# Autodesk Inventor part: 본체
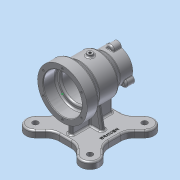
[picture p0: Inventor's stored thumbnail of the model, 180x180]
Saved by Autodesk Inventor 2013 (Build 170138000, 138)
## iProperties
Created: 2017-03
Part Number: 본체
Material: 알루미늄 6061
Document SubType Name: Modeling
Designer: Administrator
Density: 2.71 g/cm^3
Mass: 995.698 g
Surface Area: 858.98 cm^2
Volume: 367.416 cm^3
Author: Administrator
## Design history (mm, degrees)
sketch "스케치1"
  geometry: 1 further point
sketch "스케치2"
  geometry: L1 (0, 0)-(100, 0); L2 (0, 35)-(23, 35); L3 (23, 35)-(23, 26); L4 (23, 26)-(70, 26); L5 (70, 26)-(70, 17.5); L6 (70, 17.5)-(100, 17.5); L7 (100, 17.5)-(100, 27.5); L8 (100, 27.5)-(77, 27.5); L9 (77, 27.5)-(65, 36); L10 (65, 36)-(31, 36); L11 (31, 36)-(20, 45); L12 (20, 45)-(0, 45); L13 (0, 45)-(0, 35)
  constraints: 26 end point, 8 parallel, 2 perpendicular, 2 point on line, 1 horizontal
  dimensions: "d0" = 100 distance of L1.start L1.end; "d1" = 35 diameter of L6 L1; "d2" = 52 diameter of L4 L1; "d3" = 70 diameter of L2 L1; "d4" = 55 diameter of L8 L1; "d5" = 72 diameter of L10 L1; "d6" = 90 diameter of L12 L1; "d7" = 23 distance between parallel lines of L3 L13; "d8" = 47 distance between parallel lines of L5 L3; "d9" = 20 distance of L11.end L12.end; "d10" = 31 distance from line of L10.end L13; "d11" = 65 distance from line of L13 L9.end; "d12" = 23 distance of L7.end L8.end
revolve "회전1" sketch "스케치2" stored, may be unused: angle "d13" = 90 deg
chamfer "모따기1" distance "d25" = 1; stored, may be unused: second distance "d26" = 2, angle "d27" = 45 deg
node "작업 평면1"
sketch "스케치4"
  geometry: L1 (45, 5)-(-45, 5); L2 (-45, 5)-(-45, 95); L3 (-45, 95)-(45, 95); L4 (45, 95)-(45, 5); L5 (45, 5)-(-45, 95); L6 (-45, 5)-(45, 95); 2 further points
  constraints: 12 end point, 2 midpoint, 2 parallel, 1 horizontal, 1 perpendicular
  dimensions: "d29" = 90 distance of L2.end L3.end; "d31" = 90 distance of L1.end L2.end; "d32" = 0 horizontal distance of point (0, 0) point (0, 50); "d33" = 50 distance of point (0, 0) point (0, 50)
extrude "돌출2" join sketch "스케치4" distance "d34" = 12; taper "d35" = 0 deg
sketch "스케치5" dims "d36" = 140
  geometry: L1 (45, 5)-(-45, 5) reference; L2 (45, 95)-(45, 5) reference; L3 (-45, 95)-(45, 95) reference; L4 (-45, 5)-(-45, 95) reference; L5 (-45, 50)-(45, 50); L6 (0, 95)-(0, 5); L7 (49.497, 99.497)-(0, 50); L8 (24.042, 50)-(61.518, 87.477); L9 (0, 74.042)-(37.477, 111.518); A1 r 17 centre (49.497, 99.497) between (37.477, 111.518) and (61.518, 87.477); 1 further point
  constraints: 10 end point, 5 midpoint, 2 point on circle, 2 point on line, 2 tangent, 1 centre point, 3 other
  dimensions: "d38" = 45 deg angle of L5 L7; "d40" = 34 diameter of A1; "d41" = 45 deg angle of L5 L8; "d42" = 45 deg angle of L6 L9
extrude "돌출3" join sketch "스케치5" distance "d43" = 12; taper "d44" = 0 deg
sketch "스케치6"
  geometry: L1 (-45, 5)-(45, 5) reference; L2 (45, 5)-(45, 95) reference; C1 r 0.5 at (0, 50); 1 further point
  constraints: 1 centre point
  dimensions: "d45" = 45 distance from line of L1 C1.centre; "d46" = 45 distance from line of L2 C1.centre; "d47" = 1 diameter of C1
extrude "돌출4" join sketch "스케치6" distance "d48" = 5; taper "d49" = 0 deg
fillet "모깎기3" dims "d53" = 25
fillet "모깎기4" dims "d54" = 3
fillet "모깎기5" dims "d55" = 3
chamfer "모따기2" distance "d56" = 1; stored, may be unused: second distance "d57" = 2, angle "d58" = 45 deg
node "작업 평면2"
sketch "스케치11"
  geometry: L1 (-4, 87)-(4, 87); L2 (4, 87)-(4, 13); L3 (4, 13)-(-4, 13); L4 (-4, 13)-(-4, 87); L5 (-4, 87)-(4, 13); L6 (4, 87)-(-4, 13); C1 r 0.5 at (0, 50) reference; 1 further point
  constraints: 12 end point, 2 midpoint, 2 parallel, 1 horizontal, 1 perpendicular
  dimensions: "d85" = 8 distance between parallel lines of L4 L2; "d87" = 74 distance between parallel lines of L1 L3
extrude "돌출7" join sketch "스케치11" stored distance "d88" = 8; taper "d89" = 0 deg
node "작업 평면3"
sketch "스케치12"
  geometry: L1 (-4, -70)-(4, -70) reference; L2 (4, -70)-(-4, -70) reference; L3 (-30.402, -70)-(-10.603, -70) reference; L4 (-39.598, -70)-(-30.402, -70) reference; L5 (-59.397, -70)-(-39.598, -70) reference; L6 (-50.201, -70)-(-59.397, -70) reference; L7 (-42, -70)-(-50.201, -70) reference; L8 (-50.201, -70)-(-42, -70) reference; L9 (-59.397, -70)-(-50.201, -70) reference; L10 (-39.598, -70)-(-59.397, -70) reference; L11 (-30.402, -70)-(-39.598, -70) reference; L12 (-10.603, -70)-(-30.402, -70) reference; L13 (10.603, -70)-(-10.603, -70) reference; L14 (30.402, -70)-(10.603, -70) reference; L15 (39.598, -70)-(30.402, -70) reference; L16 (59.397, -70)-(39.598, -70) reference; L17 (50.201, -70)-(59.397, -70) reference; L18 (42, -70)-(50.201, -70) reference; L19 (50.201, -70)-(42, -70) reference; L20 (59.397, -70)-(50.201, -70) reference; L21 (39.598, -70)-(59.397, -70) reference; L22 (30.402, -70)-(39.598, -70) reference; L23 (10.603, -70)-(30.402, -70) reference; L24 (-10.603, -70)-(10.603, -70) reference; L25 (-25, -70)-(-18.14, -31.096); A1 r 36 centre (0, 0) between (4, -35.777) and (-4, -35.777) reference; A2 r 36 centre (0, 0) between (4, -35.777) and (-4, -35.777) reference; 1 further point
  constraints: 2 end point, 2 point on circle, 1 point on line
  dimensions: "d91" = 25 horizontal distance of point (0, 0) L25.start; "d92" = 100 deg angle of L11 L25
feature "리브3" sketch "스케치12" dims "d93" = 1, "d94" = 4, "d95" = 0, "d96" = 0, "d97" = 1, "d98" = 1
sketch "스케치13"
  geometry: L1 (-10.603, -70)-(-30.402, -70) reference; L2 (-25, -70)-(-18.14, -31.096); A1 r 36 centre (0, 0) between (4, -35.777) and (-4, -35.777) reference; 1 further point
  constraints: 2 end point, 1 point on circle, 1 point on line
  dimensions: "d99" = 25 horizontal distance of point (0, 0) L2.start; "d100" = 100 deg angle of L1 L2
feature "리브4" sketch "스케치13" dims "d101" = 1, "d102" = 4, "d103" = 0, "d104" = 0, "d105" = 1, "d106" = 1
sketch "스케치14"
  geometry: L1 (30.402, -70)-(10.603, -70) reference; L2 (25, -70)-(18.14, -31.096); A1 r 36 centre (0, 0) between (4, -35.777) and (-4, -35.777) reference; 1 further point
  constraints: 2 end point, 1 point on circle, 1 point on line
  dimensions: "d107" = 25 horizontal distance of point (0, 0) L2.start; "d108" = 100 deg angle of L1 L2
feature "리브5" sketch "스케치14" dims "d109" = 1, "d110" = 4, "d111" = 0, "d112" = 0, "d113" = 1, "d114" = 1
sketch "스케치15"
  geometry: L1 (4, -70)-(25, -70) reference; L2 (30.402, -70)-(10.603, -70) reference; L3 (25, -70)-(18.14, -31.096); A1 r 36 centre (0, 0) between (4, -35.777) and (-4, -35.777) reference; 1 further point
  constraints: 2 end point, 1 point on circle, 1 point on line
  dimensions: "d115" = 25 horizontal distance of point (0, 0) L3.start; "d116" = 100 deg angle of L1 L3
feature "리브6" sketch "스케치15" dims "d117" = 1, "d118" = 4, "d119" = 0, "d120" = 0, "d121" = 1, "d122" = 1
fillet "모깎기8" dims "d123" = 3
fillet "모깎기9" dims "d124" = 3
fillet "모깎기10" dims "d125" = 3
fillet "모깎기11" dims "d126" = 3
fillet "모깎기12" dims "d127" = 3
sketch "스케치16"
  geometry: C1 r 5 at (-49.497, 0.503); C2 r 5 at (-49.497, 99.497); C3 r 5 at (49.497, 99.497); C4 r 5 at (49.497, 0.503); A1 r 14 centre (49.497, 99.497) between (59.397, 89.598) and (39.598, 109.397) reference; A2 r 14 centre (-49.497, 99.497) between (-39.598, 109.397) and (-59.397, 89.598) reference; A3 r 14 centre (-49.497, 0.503) between (-59.397, 10.402) and (-39.598, -9.397) reference; A4 r 14 centre (49.497, 0.503) between (39.598, -9.397) and (59.397, 10.402) reference; 1 further point
  constraints: 4 centre point, 4 coincident, 3 equal radius
  dimensions: "d128" = 10 diameter of C1
extrude "돌출8" cut sketch "스케치16" stored distance "d130" = 8; taper "d131" = 0 deg
sketch "스케치17"
  geometry: C1 r 27.5 at (0, 0) reference; C2 r 7 at (0, -27.5)
  constraints: 1 centre point
  dimensions: "d132" = 0 horizontal distance of C1.centre C2.centre; "d133" = 27.5 distance of C2.centre C1.centre; "d134" = 14 diameter of C2
extrude "돌출9" join sketch "스케치17" distance "d135" = 15; taper "d136" = 0 deg
fillet "모깎기13" dims "d140" = 3
fillet "모깎기14" dims "d141" = 1
node "작업 평면4"
sketch "스케치18"
  geometry: C1 r 5 at (0, 50); 1 further point
  constraints: 1 centre point
  dimensions: "d143" = 0 horizontal distance of point (0, 0) C1.centre; "d144" = 50 distance of C1.centre point (0, 0); "d145" = 10 diameter of C1
extrude "돌출10" join sketch "스케치18" stored distance "d146" = 4; taper "d147" = 0 deg
fillet "모깎기15" dims "d148" = 3
sketch "스케치19"
  geometry: C1 r 5 at (0, 0) reference; C2 r 2.5 at (0, 0); 1 further point
  constraints: 1 centre point, 1 coincident
  dimensions: "d149" = 5 diameter of C2
hole "구멍1" sketch "스케치19" at (0, 0) diameter "d151" = 4.459; stored, may be unused: countersink angle "d155" = 90 deg, drill point angle "d157" = 118 deg; dims "d152" = 6, "d153" = 4, "d154" = 2, "d156" = 8
sketch "스케치20"
  geometry: C1 r 45 at (0, 0) reference; C2 r 2 at (0, -40)
  constraints: 1 centre point
  dimensions: "d158" = 0 horizontal distance of C1.centre C2.centre; "d159" = 40 distance of C2.centre C1.centre; "d160" = 4 diameter of C2
hole "구멍2" sketch "스케치20" at (0, -40) diameter "d161" = 3.459; stored, may be unused: countersink angle "d165" = 90 deg, drill point angle "d167" = 118 deg; dims "d162" = 9, "d163" = 4, "d164" = 2, "d166" = 11
sketch "스케치21"
  geometry: L1 (1, 90)-(-1, 90) reference; L2 (27.517, 49)-(27.517, 51) reference; L3 (-1, 10)-(1, 10) reference; L4 (-27.517, 51)-(-27.517, 49) reference; L5 (56.927, 33.408)-(56.927, 66.592); L6 (56.927, 66.592)-(13.073, 66.592); L7 (13.073, 66.592)-(13.073, 33.408); L8 (13.073, 33.408)-(56.927, 33.408); L9 (35, 33.408)-(35, 66.592); L10 (13.073, 50)-(56.927, 50); L11 (0, 90)-(0, 10); L12 (27.517, 50)-(-27.517, 50); 1 further point
  constraints: 8 end point, 8 midpoint, 2 other
  dimensions: "d171" = 35 distance from line of point (0, 0) L9; "d173" = 0 distance between parallel lines of L12 L10
extrude "돌출11" join sketch "스케치21" distance "d174" = 0.5; taper "d175" = 0 deg
sketch "스케치22"
  geometry: C1 r 2 at (0, 0); A1 r 7 centre (0, 0) between (-6.999, 0.127) and (6.999, 0.127) reference
  constraints: 1 centre point, 1 coincident
  dimensions: "d176" = 4 diameter of C1
hole "구멍3" sketch "스케치22" at (0, 0) diameter "d178" = 3.459; stored, may be unused: countersink angle "d182" = 90 deg, drill point angle "d184" = 118 deg; dims "d179" = 9, "d180" = 4, "d181" = 2, "d183" = 11
sketch "스케치23"
  geometry: C1 r 5 at (0, 50) reference; C2 r 5 at (0, 50); 1 further point
  constraints: 1 centre point, 1 coincident, 1 concentric
extrude "돌출12" join sketch "스케치23" stored distance "d188" = 10; taper "d189" = 0 deg
node "솔리드1"
pattern_circular "원형 패턴2" dims angle "d51" = 360 deg
pattern_circular "원형 패턴3" dims angle "d138" = 360 deg
pattern_circular "원형 패턴4" dims angle "d169" = 360 deg
pattern_circular "원형 패턴5" dims angle "d186" = 360 deg
node "투영된 루프5"
node "투영된 루프6"
other parameters: "d28" = -82
